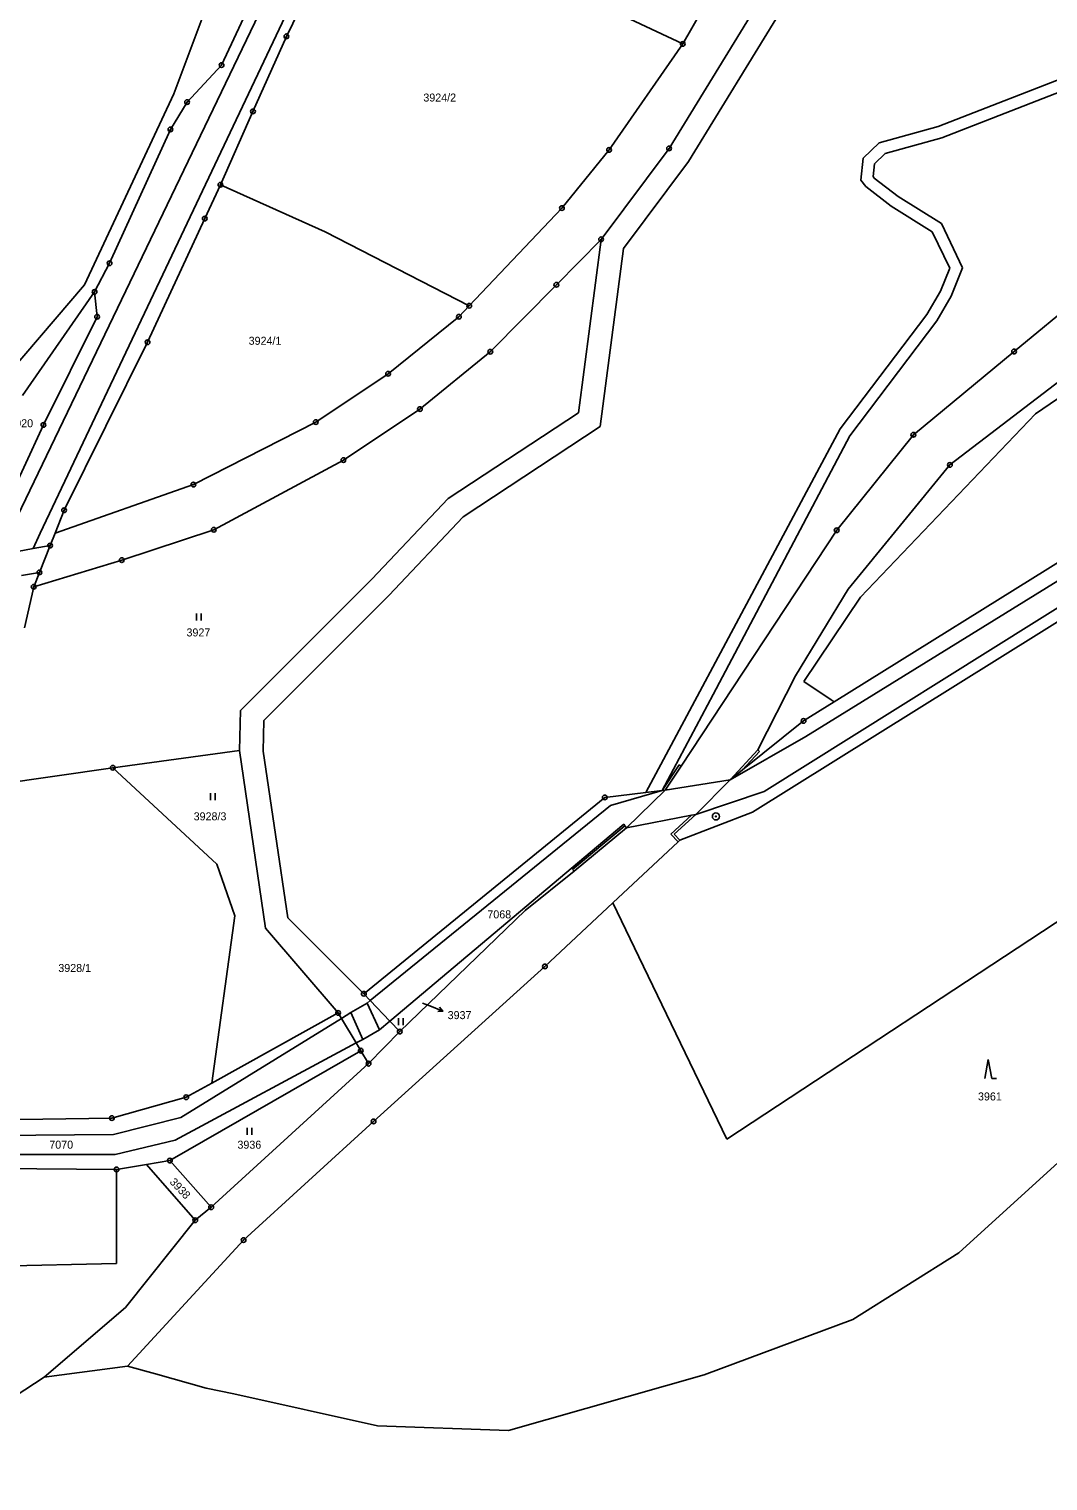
# Model space of a CAD drawing. Extents: x -593183 to -588034, y -1130415 to -1124994.
# Drawn here: x -592483.7 to -592267.4, y -1130412.8 to -1130104.5 of the extents above; entities that cross this region are included whole.
import ezdxf

# ---------------------------------------------------------------- set-up
doc = ezdxf.new("R2010")
doc.units = 0
for name, color, linetype in [('Vrstva 1', 7, 'Continuous'), ('Vrstva 13', 7, 'Continuous'), ('Vrstva 16', 7, 'Continuous'), ('Vrstva 18', 7, 'Continuous'), ('Vrstva 24', 7, 'Continuous'), ('Vrstva 25', 7, 'Continuous'), ('Vrstva 4', 7, 'Continuous')]:
    doc.layers.add(name, color=color, linetype=linetype)

msp = doc.modelspace()

# ---------------------------------------------------------------- linework, layer by layer
at = {"layer": 'Vrstva 1'}
for p, q in [((-592442.87, -1130112.13), (-592422.49, -1130068.66)), ((-592429.1, -1130106.03), (-592413.87, -1130075.19)), ((-592413.87, -1130075.19), (-592344.91, -1130107.65)), ((-592347.83, -1130129.82), (-592326.39, -1130094.84)), ((-592453, -1130118.27), (-592445.81, -1130098.99)), ((-592344.91, -1130107.65), (-592338.87, -1130097.1)), ((-592343.69, -1130132.63), (-592323.81, -1130100.2)), ((-592436.19, -1130121.97), (-592429.1, -1130106.03)), ((-592360.56, -1130130.15), (-592344.91, -1130107.65)), ((-592248.55, -1130108.76), (-592290.71, -1130125.21)), ((-592274.57, -1130172.96), (-592194.8, -1130107.03)), ((-592450.18, -1130119.99), (-592442.87, -1130112.13)), ((-592289.92, -1130127.59), (-592247.21, -1130110.92)), ((-592471.97, -1130158.83), (-592453, -1130118.27)), ((-592453.72, -1130125.79), (-592450.18, -1130119.99)), ((-592443.1, -1130137.55), (-592436.19, -1130121.97)), ((-592466.64, -1130154.21), (-592453.72, -1130125.79)), ((-592290.71, -1130125.21), (-592303.21, -1130128.67)), ((-592301.94, -1130130.91), (-592289.92, -1130127.59)), ((-592370.6, -1130142.5), (-592360.56, -1130130.15)), ((-592362.28, -1130149.14), (-592347.83, -1130129.82)), ((-592303.21, -1130128.67), (-592306.62, -1130131.93)), ((-592357.49, -1130151.09), (-592343.69, -1130132.63)), ((-592306.62, -1130131.93), (-592307.11, -1130136.57)), ((-592304.23, -1130133.1), (-592304.52, -1130135.82)), ((-592304.23, -1130133.1), (-592301.94, -1130130.91)), ((-592307.11, -1130136.57), (-592306.04, -1130137.93)), ((-592304.52, -1130135.82), (-592304.26, -1130136.14)), ((-592304.26, -1130136.14), (-592299.21, -1130140.07)), ((-592446.44, -1130144.73), (-592443.1, -1130137.55)), ((-592443.1, -1130137.55), (-592420.85, -1130147.55)), ((-592306.04, -1130137.93), (-592300.64, -1130142.12)), ((-592289.99, -1130145.79), (-592299.21, -1130140.07)), ((-592390.28, -1130163.25), (-592370.6, -1130142.5)), ((-592300.64, -1130142.12), (-592291.93, -1130147.53)), ((-592458.58, -1130170.99), (-592446.44, -1130144.73)), ((-592285.51, -1130155.16), (-592289.99, -1130145.79)), ((-592420.85, -1130147.55), (-592390.28, -1130163.25)), ((-592371.77, -1130158.8), (-592362.28, -1130149.14)), ((-592362.28, -1130149.14), (-592367.09, -1130185.96)), ((-592291.93, -1130147.53), (-592288.24, -1130155.25)), ((-592362.43, -1130188.88), (-592357.49, -1130151.09)), ((-592469.83, -1130160.31), (-592466.64, -1130154.21)), ((-592288.24, -1130155.25), (-592290.19, -1130160.14)), ((-592287.94, -1130161.24), (-592285.51, -1130155.16)), ((-592487.77, -1130177.27), (-592471.97, -1130158.83)), ((-592485.1, -1130182.3), (-592469.83, -1130160.31)), ((-592469.83, -1130160.31), (-592469.28, -1130165.59)), ((-592385.79, -1130173), (-592371.77, -1130158.8)), ((-592290.19, -1130160.14), (-592293.06, -1130165.08)), ((-592290.97, -1130166.47), (-592287.94, -1130161.24)), ((-592392.46, -1130165.59), (-592390.28, -1130163.25)), ((-592270.02, -1130186.17), (-592235.5, -1130162.55)), ((-592469.28, -1130165.59), (-592480.68, -1130188.56)), ((-592407.51, -1130177.7), (-592392.46, -1130165.59)), ((-592293.06, -1130165.08), (-592311.47, -1130189.39)), ((-592309.48, -1130190.9), (-592290.97, -1130166.47)), ((-592476.3, -1130206.67), (-592458.58, -1130170.99)), ((-592400.73, -1130185.2), (-592385.79, -1130173)), ((-592295.96, -1130190.64), (-592274.57, -1130172.96)), ((-592422.86, -1130187.96), (-592407.51, -1130177.7)), ((-592288.21, -1130197.04), (-592263.56, -1130178.19)), ((-592416.97, -1130196.01), (-592400.73, -1130185.2)), ((-592394.77, -1130204.18), (-592367.09, -1130185.96)), ((-592307.21, -1130225.13), (-592270.02, -1130186.17)), ((-592480.68, -1130188.56), (-592489.01, -1130206.64)), ((-592448.84, -1130201.22), (-592422.86, -1130187.96)), ((-592391.54, -1130208.04), (-592362.43, -1130188.88)), ((-592311.47, -1130189.39), (-592349.02, -1130259.59)), ((-592338.5, -1130245.83), (-592309.48, -1130190.9)), ((-592312.24, -1130210.93), (-592295.96, -1130190.64)), ((-592444.51, -1130210.81), (-592416.97, -1130196.01)), ((-592312.78, -1130247.35), (-592232.34, -1130197.24)), ((-592309.78, -1130223.4), (-592288.21, -1130197.04)), ((-592478.21, -1130211.54), (-592448.84, -1130201.22)), ((-592410.96, -1130221.29), (-592394.77, -1130204.18)), ((-592478.21, -1130211.54), (-592476.3, -1130206.67)), ((-592330.12, -1130270.81), (-592226.72, -1130206.2)), ((-592464.06, -1130217.27), (-592444.51, -1130210.81)), ((-592407.37, -1130224.77), (-592391.54, -1130208.04)), ((-592345.29, -1130260.99), (-592312.24, -1130210.93)), ((-592479.26, -1130214.17), (-592478.21, -1130211.54)), ((-592489.55, -1130216.04), (-592482.84, -1130214.82)), ((-592482.84, -1130214.82), (-592479.26, -1130214.17)), ((-592481.55, -1130219.88), (-592479.26, -1130214.17)), ((-592335.59, -1130340.25), (-592145.5, -1130215.1)), ((-592485.34, -1130220.52), (-592481.55, -1130219.88)), ((-592482.76, -1130222.91), (-592464.06, -1130217.27)), ((-592482.76, -1130222.91), (-592481.55, -1130219.88)), ((-592484.73, -1130231.63), (-592482.76, -1130222.91)), ((-592438.82, -1130249.22), (-592410.96, -1130221.29)), ((-592433.88, -1130251.35), (-592407.37, -1130224.77)), ((-592320.97, -1130241.85), (-592309.78, -1130223.4)), ((-592307.21, -1130225.13), (-592319.23, -1130243.02)), ((-592329, -1130257.55), (-592320.97, -1130241.85)), ((-592319.23, -1130243.02), (-592313.38, -1130246.95)), ((-592338.5, -1130245.83), (-592349.31, -1130266.19)), ((-592319.28, -1130251.4), (-592312.78, -1130247.35)), ((-592313.38, -1130246.95), (-592312.78, -1130247.35)), ((-592439.06, -1130257.72), (-592438.82, -1130249.22)), ((-592434.06, -1130257.86), (-592433.88, -1130251.35)), ((-592332.23, -1130261.81), (-592319.28, -1130251.4)), ((-592465.98, -1130261.36), (-592439.06, -1130257.72)), ((-592439.06, -1130257.72), (-592433.55, -1130295.42)), ((-592428.81, -1130293.26), (-592434.06, -1130257.86)), ((-592352.77, -1130266.61), (-592349.02, -1130259.59)), ((-592334.87, -1130263.93), (-592329, -1130257.55)), ((-592493.02, -1130265.28), (-592465.98, -1130261.36)), ((-592465.98, -1130261.36), (-592443.88, -1130281.86)), ((-592348.66, -1130266.11), (-592345.29, -1130260.99)), ((-592334.87, -1130263.93), (-592332.23, -1130261.81)), ((-592356.89, -1130274.1), (-592348.66, -1130266.11)), ((-592352.77, -1130266.61), (-592349.31, -1130266.19)), ((-592349.31, -1130266.19), (-592348.66, -1130266.11)), ((-592334.87, -1130263.93), (-592342.14, -1130271.26)), ((-592412.65, -1130309.34), (-592361.5, -1130267.67)), ((-592361.5, -1130267.67), (-592352.77, -1130266.61)), ((-592343.07, -1130271.44), (-592347.45, -1130275.43)), ((-592345.57, -1130276.73), (-592330.12, -1130270.81)), ((-592342.14, -1130271.26), (-592343.07, -1130271.44)), ((-592407.11, -1130315.18), (-592357.43, -1130273.35)), ((-592367.99, -1130283.33), (-592356.89, -1130274.1)), ((-592357.21, -1130273.71), (-592357.43, -1130273.35)), ((-592356.89, -1130274.1), (-592357.21, -1130273.71)), ((-592347.45, -1130275.43), (-592345.93, -1130277.07)), ((-592359.8, -1130290.07), (-592345.93, -1130277.07)), ((-592345.93, -1130277.07), (-592345.57, -1130276.73)), ((-592443.88, -1130281.86), (-592440.03, -1130292.81)), ((-592378.41, -1130291.65), (-592367.99, -1130283.33)), ((-592374.19, -1130303.56), (-592359.8, -1130290.07)), ((-592359.8, -1130290.07), (-592354.26, -1130301.52)), ((-592440.03, -1130292.81), (-592444.95, -1130328.33)), ((-592412.65, -1130309.34), (-592428.81, -1130293.26)), ((-592405.01, -1130317.38), (-592378.41, -1130291.65)), ((-592433.55, -1130295.42), (-592418.12, -1130313.41)), ((-592354.26, -1130301.52), (-592335.59, -1130340.25)), ((-592410.57, -1130336.47), (-592374.19, -1130303.56)), ((-592412.65, -1130309.34), (-592411.27, -1130310.79)), ((-592411.27, -1130310.79), (-592407.11, -1130315.18)), ((-592418.12, -1130313.41), (-592444.95, -1130328.33)), ((-592418.12, -1130313.41), (-592417.41, -1130314.59)), ((-592417.41, -1130314.59), (-592414.27, -1130319.81)), ((-592407.11, -1130315.18), (-592405.01, -1130317.38)), ((-592411.63, -1130324.2), (-592405.01, -1130317.38)), ((-592453.84, -1130344.78), (-592413.29, -1130321.44)), ((-592414.27, -1130319.81), (-592413.29, -1130321.44)), ((-592413.29, -1130321.44), (-592411.63, -1130324.2)), ((-592445.07, -1130354.68), (-592411.63, -1130324.2)), ((-592444.95, -1130328.33), (-592450.37, -1130331.34)), ((-592450.37, -1130331.34), (-592466.15, -1130335.75)), ((-592466.15, -1130335.75), (-592498.29, -1130336.22)), ((-592438.19, -1130361.66), (-592410.57, -1130336.47)), ((-592513.5, -1130346.25), (-592465.17, -1130346.67)), ((-592465.17, -1130346.67), (-592458.77, -1130345.6)), ((-592465.17, -1130366.67), (-592465.17, -1130346.67)), ((-592458.77, -1130345.6), (-592453.84, -1130344.78)), ((-592448.45, -1130357.44), (-592458.77, -1130345.6)), ((-592453.84, -1130344.78), (-592445.07, -1130354.68)), ((-592445.07, -1130354.68), (-592448.45, -1130357.44)), ((-592448.45, -1130357.44), (-592463.26, -1130376.01)), ((-592462.85, -1130388.41), (-592438.19, -1130361.66)), ((-592513.72, -1130367.75), (-592465.17, -1130366.67)), ((-592463.26, -1130376.01), (-592480.56, -1130390.77))]:
    msp.add_line(p, q, dxfattribs=at)
at = {"layer": 'Vrstva 13'}
for p, q in [((-592286.28, -1130364.36), (-592263.67, -1130343.74)), ((-592308.84, -1130378.51), (-592286.28, -1130364.36)), ((-592340.4, -1130390.27), (-592308.84, -1130378.51)), ((-592480.56, -1130390.77), (-592462.85, -1130388.41)), ((-592462.85, -1130388.41), (-592456.87, -1130390.1)), ((-592514.19, -1130412.82), (-592480.56, -1130390.77)), ((-592456.87, -1130390.1), (-592446.14, -1130393.14)), ((-592381.95, -1130402.13), (-592340.4, -1130390.27)), ((-592446.14, -1130393.14), (-592440.29, -1130394.34)), ((-592440.29, -1130394.34), (-592409.78, -1130401.12)), ((-592409.78, -1130401.12), (-592381.95, -1130402.13))]:
    msp.add_line(p, q, dxfattribs=at)
at = {"layer": 'Vrstva 16'}
msp.add_line((-592400.2, -1130311.32), (-592398.64, -1130311.94), dxfattribs=at)
at = {"layer": 'Vrstva 24'}
for centre, radius in [((-592429.1, -1130106.03), 0.5), ((-592429.1, -1130106.03), 0.0327), ((-592344.91, -1130107.65), 0.5), ((-592344.91, -1130107.65), 0.0327), ((-592442.87, -1130112.13), 0.5), ((-592442.87, -1130112.13), 0.0327), ((-592450.18, -1130119.99), 0.5), ((-592450.18, -1130119.99), 0.0327), ((-592436.19, -1130121.97), 0.5), ((-592436.19, -1130121.97), 0.0327), ((-592453.72, -1130125.79), 0.5), ((-592453.72, -1130125.79), 0.0327), ((-592360.56, -1130130.15), 0.5), ((-592360.56, -1130130.15), 0.0327), ((-592347.83, -1130129.82), 0.5), ((-592347.83, -1130129.82), 0.0327), ((-592443.1, -1130137.55), 0.5), ((-592443.1, -1130137.55), 0.0327), ((-592370.6, -1130142.5), 0.5), ((-592370.6, -1130142.5), 0.0327), ((-592446.44, -1130144.73), 0.5), ((-592446.44, -1130144.73), 0.0327), ((-592362.28, -1130149.14), 0.5), ((-592362.28, -1130149.14), 0.0327), ((-592466.64, -1130154.21), 0.5), ((-592466.64, -1130154.21), 0.0327), ((-592371.77, -1130158.8), 0.5), ((-592469.83, -1130160.31), 0.5), ((-592469.83, -1130160.31), 0.0327), ((-592371.77, -1130158.8), 0.0327), ((-592390.28, -1130163.25), 0.5), ((-592390.28, -1130163.25), 0.0327), ((-592469.28, -1130165.59), 0.5), ((-592469.28, -1130165.59), 0.0327), ((-592392.46, -1130165.59), 0.5), ((-592392.46, -1130165.59), 0.0327), ((-592458.58, -1130170.99), 0.5), ((-592458.58, -1130170.99), 0.0327), ((-592385.79, -1130173), 0.5), ((-592385.79, -1130173), 0.0327), ((-592274.57, -1130172.96), 0.5), ((-592274.57, -1130172.96), 0.0327), ((-592407.51, -1130177.7), 0.5), ((-592407.51, -1130177.7), 0.0327), ((-592400.73, -1130185.2), 0.5), ((-592400.73, -1130185.2), 0.0327), ((-592480.68, -1130188.56), 0.5), ((-592480.68, -1130188.56), 0.0327), ((-592422.86, -1130187.96), 0.5), ((-592422.86, -1130187.96), 0.0327), ((-592295.96, -1130190.64), 0.5), ((-592295.96, -1130190.64), 0.0327), ((-592416.97, -1130196.01), 0.5), ((-592416.97, -1130196.01), 0.0327), ((-592288.21, -1130197.04), 0.5), ((-592288.21, -1130197.04), 0.0327), ((-592448.84, -1130201.22), 0.5), ((-592448.84, -1130201.22), 0.0327), ((-592476.3, -1130206.67), 0.5), ((-592476.3, -1130206.67), 0.0327), ((-592444.51, -1130210.81), 0.5), ((-592444.51, -1130210.81), 0.0327), ((-592312.24, -1130210.93), 0.5), ((-592312.24, -1130210.93), 0.0327), ((-592479.26, -1130214.17), 0.5), ((-592479.26, -1130214.17), 0.0327), ((-592464.06, -1130217.27), 0.5), ((-592481.55, -1130219.88), 0.5), ((-592481.55, -1130219.88), 0.0327), ((-592464.06, -1130217.27), 0.0327), ((-592482.76, -1130222.91), 0.5), ((-592482.76, -1130222.91), 0.0327), ((-592319.28, -1130251.4), 0.5), ((-592319.28, -1130251.4), 0.0327), ((-592465.98, -1130261.36), 0.5), ((-592465.98, -1130261.36), 0.0327), ((-592361.5, -1130267.67), 0.5), ((-592361.5, -1130267.67), 0.0327), ((-592337.89, -1130271.7), 0.75), ((-592337.89, -1130271.7), 0.0903), ((-592374.19, -1130303.56), 0.5), ((-592374.19, -1130303.56), 0.0327), ((-592412.65, -1130309.34), 0.5), ((-592412.65, -1130309.34), 0.0327), ((-592418.12, -1130313.41), 0.5), ((-592418.12, -1130313.41), 0.0327), ((-592405.01, -1130317.38), 0.5), ((-592405.01, -1130317.38), 0.0327), ((-592413.29, -1130321.44), 0.5), ((-592413.29, -1130321.44), 0.0327), ((-592411.63, -1130324.2), 0.5), ((-592411.63, -1130324.2), 0.0327), ((-592450.37, -1130331.34), 0.5), ((-592450.37, -1130331.34), 0.0327), ((-592466.15, -1130335.75), 0.5), ((-592466.15, -1130335.75), 0.0327), ((-592410.57, -1130336.47), 0.5), ((-592410.57, -1130336.47), 0.0327), ((-592465.17, -1130346.67), 0.5), ((-592465.17, -1130346.67), 0.0327), ((-592453.84, -1130344.78), 0.5), ((-592453.84, -1130344.78), 0.0327), ((-592445.07, -1130354.68), 0.5), ((-592445.07, -1130354.68), 0.0327), ((-592448.45, -1130357.44), 0.5), ((-592448.45, -1130357.44), 0.0327), ((-592438.19, -1130361.66), 0.5), ((-592438.19, -1130361.66), 0.0327)]:
    msp.add_circle(centre, radius, dxfattribs=at)
at = {"layer": 'Vrstva 25'}
for p, q in [((-592448.19, -1130228.59), (-592448.19, -1130230.09)), ((-592447.17, -1130230.09), (-592447.17, -1130228.59)), ((-592445.23, -1130266.72), (-592445.23, -1130268.22)), ((-592444.21, -1130268.22), (-592444.21, -1130266.72)), ((-592398.64, -1130311.94), (-592395.85, -1130313.04)), ((-592405.32, -1130314.52), (-592405.32, -1130316.02)), ((-592404.3, -1130316.02), (-592404.3, -1130314.52)), ((-592280.04, -1130323.35), (-592280.78, -1130327.35)), ((-592280.04, -1130323.35), (-592279.31, -1130327.35)), ((-592279.31, -1130327.35), (-592278.31, -1130327.35)), ((-592437.42, -1130337.82), (-592437.42, -1130339.32)), ((-592436.4, -1130339.32), (-592436.4, -1130337.82))]:
    msp.add_line(p, q, dxfattribs=at)
msp.add_lwpolyline([(-592396.6, -1130312.21), (-592395.85, -1130313.04), (-592396.96, -1130313.14)], dxfattribs=at)
at = {"layer": 'Vrstva 4'}
for p, q in [((-592488, -1130211.64), (-592419.57, -1130069.39)), ((-592481.41, -1130211.57), (-592415.5, -1130072.49)), ((-592318.8, -1130254.73), (-592230.54, -1130200.12)), ((-592327.67, -1130266.43), (-592228.09, -1130204.01)), ((-592482.84, -1130214.82), (-592481.41, -1130211.57)), ((-592334.87, -1130263.93), (-592318.8, -1130254.73)), ((-592332.23, -1130261.81), (-592328.63, -1130257.89)), ((-592328.63, -1130257.89), (-592329, -1130257.55)), ((-592349.31, -1130266.19), (-592345.71, -1130260.72)), ((-592345.71, -1130260.72), (-592345.29, -1130260.99)), ((-592360.28, -1130269.37), (-592349.31, -1130266.19)), ((-592348.66, -1130266.11), (-592334.87, -1130263.93)), ((-592342.14, -1130271.26), (-592327.67, -1130266.43)), ((-592411.27, -1130310.79), (-592360.28, -1130269.37)), ((-592356.89, -1130274.1), (-592343.07, -1130271.44)), ((-592342.14, -1130271.26), (-592346.74, -1130275.46)), ((-592368.31, -1130282.95), (-592357.21, -1130273.71)), ((-592346.74, -1130275.46), (-592345.57, -1130276.73)), ((-592367.99, -1130283.33), (-592368.31, -1130282.95)), ((-592415.39, -1130313.35), (-592411.93, -1130311.32)), ((-592411.93, -1130311.32), (-592411.27, -1130310.79)), ((-592411.93, -1130311.32), (-592409.32, -1130317.04)), ((-592451.48, -1130335.62), (-592417.41, -1130314.59)), ((-592417.41, -1130314.59), (-592415.39, -1130313.35)), ((-592412.84, -1130319.04), (-592415.39, -1130313.35)), ((-592409.32, -1130317.04), (-592407.11, -1130315.18)), ((-592409.32, -1130317.04), (-592412.84, -1130319.04)), ((-592414.27, -1130319.81), (-592452.72, -1130340.44)), ((-592412.84, -1130319.04), (-592414.27, -1130319.81)), ((-592465.84, -1130339.22), (-592451.48, -1130335.62)), ((-592502.62, -1130339.57), (-592465.84, -1130339.22)), ((-592465.46, -1130343.49), (-592452.72, -1130340.44)), ((-592503.46, -1130343.53), (-592465.46, -1130343.49))]:
    msp.add_line(p, q, dxfattribs=at)

# ---------------------------------------------------------------- texts
at = {"layer": 'Vrstva 16'}
msp.add_text('3937', height=1.7, dxfattribs=at).set_placement((-592394.85, -1130314.74))
at = {"layer": 'Vrstva 18'}
for s, height, p in [('3924/2', 1.7, (-592400.01, -1130119.88)), ('3924/1', 1.7, (-592437.11, -1130171.53)), ('3920', 1.7, (-592487.94, -1130189.05)), ('3927', 1.7, (-592450.31, -1130233.47)), ('3928/3', 1.7, (-592448.79, -1130272.53)), ('7068', 1.7, (-592386.42, -1130293.34)), ('3928/1', 1.7, (-592477.53, -1130304.73)), ('3937', 0.1, (-592400.2, -1130311.32)), ('3961', 1.7, (-592282.23, -1130332.01)), ('7070', 1.7, (-592479.44, -1130342.26)), ('3936', 1.7, (-592439.49, -1130342.26))]:
    msp.add_text(s, height=height, dxfattribs=at).set_placement(p)
msp.add_text('3938', height=1.7, rotation=313.4144, dxfattribs=at).set_placement((-592454.01, -1130349.44))

doc.saveas('drawing.dxf')
